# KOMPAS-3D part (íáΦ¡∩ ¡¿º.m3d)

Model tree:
1. Эскиз:1
2. Операция выдавливания:1
     Расстояние 1 = 1
3. Эскиз:3
4. Операция выдавливания:3
     Расстояние 1 = 5
5. Эскиз:4
6. Операция выдавливания:4
     Расстояние 1 = 0.5
7. Эскиз:9
8. Отверстие:2
9. Эскиз:10
10. Операция выдавливания:7
     Расстояние 1 = 12.5
11. Эскиз:11
12. Операция выдавливания:8
     Расстояние 1 = 20
13. Эскиз:12
14. Отверстие:3
15. Эскиз:13
16. Вырезать элемент выдавливания:2
     Расстояние 1 = 5
17. Массив по концентрической сетке:1  (with: Вырезать элемент выдавливания:2)  (labels: Экземпляр ( 1, 1 ); Экземпляр ( 1, 2 ); Экземпляр ( 1, 3 ); Экземпляр ( 1, 4 ))
     N 2 = 70; Шаг 2 = 360; Номер 2 = 1
18. Эскиз:14
19. Вырезать элемент выдавливания:3
     Расстояние 1 = 1
20. Эскиз:15
21. Операция выдавливания:9
     Расстояние 1 = 22.4
22. Эскиз:16
23. Вырезать элемент выдавливания:4
     Расстояние 1 = 97.9895
24. Фаска:1
     Угол = 45; Длина 1 = 1; Длина 2 = 1
25. Скругление:1
     Радиус = 0.5
26. Скругление:2
     Радиус = 0.5
27. Скругление:4
     Радиус = 0.5
28. Эскиз:17
29. Вырезать элемент выдавливания:5
     Расстояние 2 = 71.9895; Расстояние 1 = 97.9895

Referenced files in C:\Program Files\ASCON\KOMPAS-3D V13 Home\Sys\: holelib.lfr
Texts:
  Сплав АЛ8  ГОСТ 1583-93
  Отверстие 01
  (вариант 1)
  stalker61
